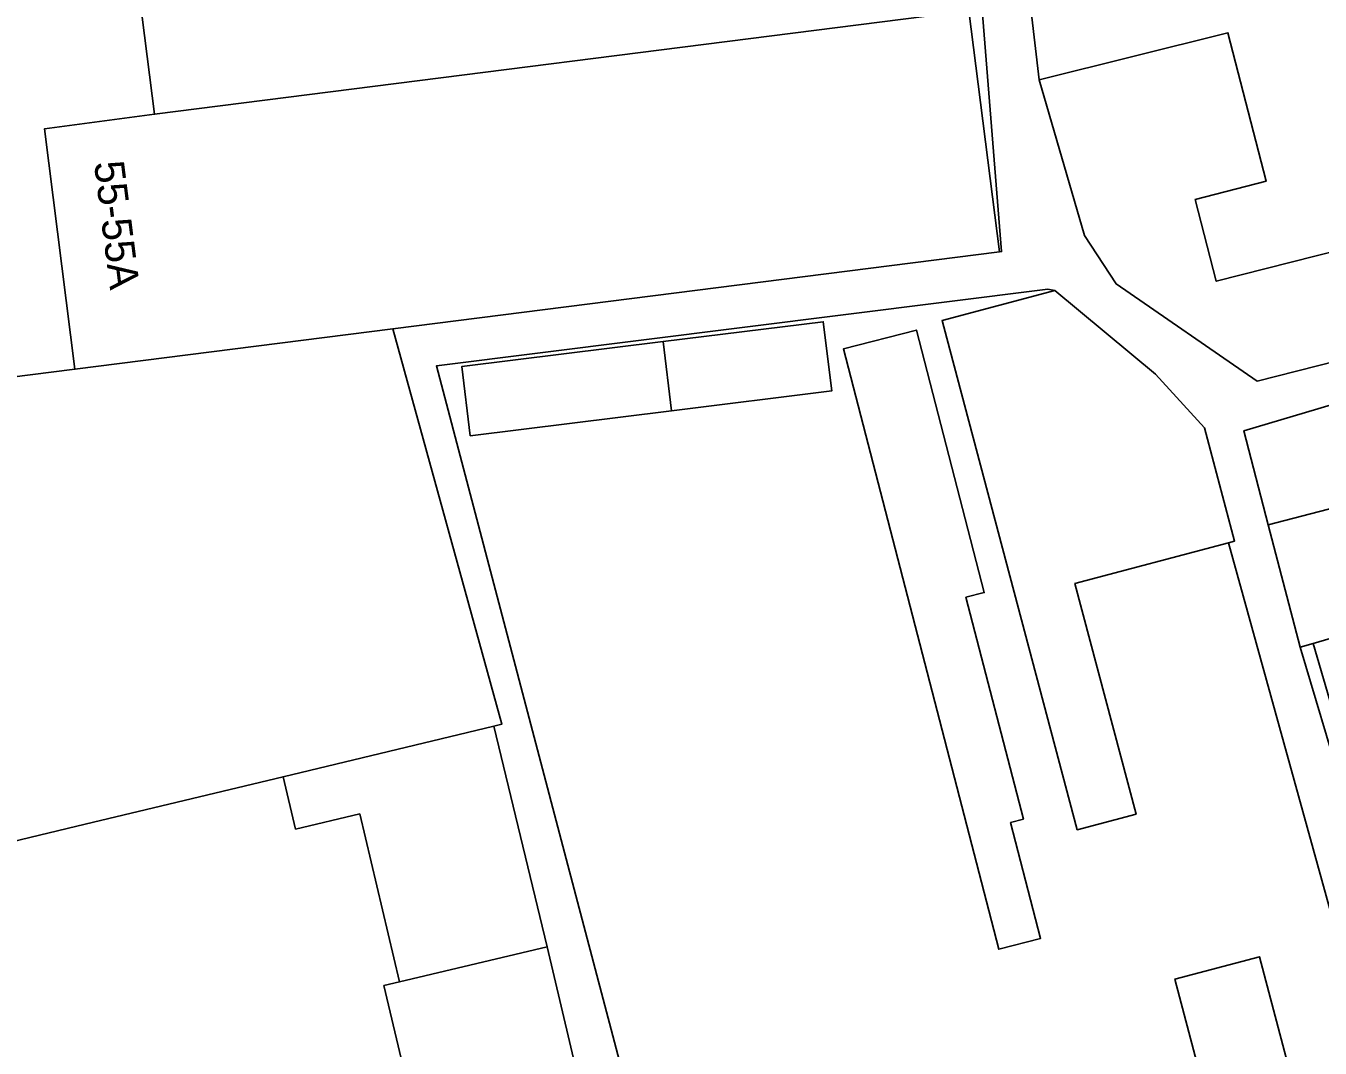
# Model space of a CAD drawing. Extents: x 159262 to 160143, y 383399 to 384319.
# Drawn here: x 159732.84 to 159776.11, y 383835.3 to 383869.47 of the extents above; entities that cross this region are included whole.
import ezdxf

# ---------------------------------------------------------------- set-up
doc = ezdxf.new("R2010")
doc.units = 0
for name, color, linetype in [('IMGEO_Erf', 7, 'Continuous'), ('IMGEO_Pand', 7, 'Continuous'), ('IMGEO_Pand_nummerreeks', 7, 'Continuous'), ('IMGEO_Voetpad_open', 7, 'Continuous')]:
    doc.layers.add(name, color=color, linetype=linetype)

msp = doc.modelspace()

# ---------------------------------------------------------------- linework, layer by layer
at = {"layer": 'IMGEO_Erf'}
for points in [[(159793.775, 383887.604), (159772.878, 383881.969), (159765.598, 383880.005), (159765.664, 383879.758), (159767.81, 383880.351), (159769.144, 383875.373), (159766.998, 383874.78), (159767.047, 383874.596), (159769.706, 383875.08), (159770.298, 383871.831), (159767.071, 383871.242), (159766.479, 383874.492), (159765.932, 383874.341), (159766.711, 383867.668), (159773.026, 383869.247), (159774.305, 383864.282), (159771.931, 383863.67), (159772.634, 383860.939), (159780.947, 383863.051)], [(159764.364, 383869.975), (159765.386, 383861.918), (159765.459, 383861.928), (159764.1, 383878.938)], [(159732.451, 383869.972), (159725.366, 383868.142), (159726.937, 383862.447), (159722.699, 383861.277), (159722.791, 383860.941), (159721.394, 383860.556), (159721.292, 383860.922), (159717.178, 383859.787), (159718.089, 383855.916), (159723.05, 383856.546), (159734.479, 383857.996), (159733.459, 383866.03), (159737.14, 383866.52), (159736.148, 383874.337)], [(159780.061, 383826.825), (159773.045, 383852.196), (159767.91, 383850.833), (159769.956, 383843.125), (159767.985, 383842.602), (159763.624, 383859.035), (159763.467, 383859.625), (159767.243, 383860.627), (159767.004, 383860.67), (159746.562, 383858.112), (159750.904, 383841.626), (159754.397, 383828.364)], [(159784.089, 383859.072), (159773.554, 383855.94), (159774.374, 383852.793), (159776.644, 383853.384)], [(159776.832, 383845.553), (159775.873, 383848.832), (159775.439, 383848.705), (159776.858, 383843.958)], [(159772.809, 383831.702), (159771.253, 383837.61), (159774.075, 383838.359), (159775.641, 383832.453)]]:
    msp.add_lwpolyline(points, dxfattribs=at)
for points in [[(159747.696, 383855.773), (159747.409, 383858.087), (159754.141, 383858.922), (159759.494, 383859.587), (159759.781, 383857.273), (159754.428, 383856.609)], [(159765.365, 383838.607), (159760.169, 383858.676), (159762.609, 383859.308), (159764.88, 383850.534), (159764.265, 383850.374), (159766.187, 383842.952), (159765.757, 383842.841), (159766.76, 383838.969)], [(159744.807, 383837.396), (159745.327, 383837.519), (159743.998, 383843.131), (159741.854, 383842.624), (159741.439, 383844.377), (159734.82, 383842.786), (159730.508, 383841.75), (159730.553, 383841.586), (159731.396, 383838.535), (159732.499, 383834.542), (159734.47, 383827.405), (159731.396, 383826.556), (159726.576, 383825.224), (159726.867, 383824.191), (159731.687, 383825.522), (159736.244, 383826.781), (159737.08, 383823.754), (159742.275, 383825.189), (159747.666, 383826.678), (159746.771, 383829.916), (159751.997, 383831.361), (159751.996, 383831.365), (159746.541, 383830.073)]]:
    msp.add_lwpolyline(points, close=True, dxfattribs=at)
at = {"layer": 'IMGEO_Pand'}
for points in [[(159763.372, 383877.791), (159736.148, 383874.337), (159737.14, 383866.52), (159764.364, 383869.975)], [(159764.364, 383869.975), (159737.14, 383866.52), (159733.459, 383866.03), (159734.479, 383857.996), (159745.107, 383859.345), (159765.386, 383861.918)], [(159773.026, 383869.247), (159766.711, 383867.668), (159768.227, 383862.468), (159769.29, 383860.847), (159774.002, 383857.6), (159782.025, 383859.638), (159781.807, 383860.328), (159781.261, 383862.057), (159780.947, 383863.051), (159772.634, 383860.939), (159771.931, 383863.67), (159774.305, 383864.282)], [(159773.045, 383852.196), (159773.245, 383852.249), (159772.24, 383856.037), (159770.608, 383857.83), (159767.243, 383860.627), (159763.467, 383859.625), (159763.624, 383859.035), (159767.985, 383842.602), (159769.956, 383843.125), (159767.91, 383850.833)], [(159754.141, 383858.922), (159754.428, 383856.609), (159759.781, 383857.273), (159759.494, 383859.587)], [(159745.107, 383859.345), (159734.479, 383857.996), (159723.05, 383856.546), (159718.089, 383855.916), (159718.524, 383854.342), (159720.384, 383854.855), (159721.039, 383852.483), (159719.214, 383851.98), (159719.446, 383851.131), (159720.089, 383848.771), (159720.571, 383847.005), (159721.214, 383844.648), (159721.703, 383842.87), (159722.354, 383840.513), (159722.636, 383839.492), (159730.553, 383841.586), (159730.508, 383841.75), (159734.82, 383842.786), (159741.439, 383844.377), (159748.488, 383846.071), (159748.754, 383846.135)], [(159760.169, 383858.676), (159765.365, 383838.607), (159766.76, 383838.969), (159765.757, 383842.841), (159766.187, 383842.952), (159764.265, 383850.374), (159764.88, 383850.534), (159762.609, 383859.308)], [(159754.141, 383858.922), (159747.409, 383858.087), (159747.696, 383855.773), (159754.428, 383856.609)], [(159776.644, 383853.384), (159774.374, 383852.793), (159775.439, 383848.705), (159775.873, 383848.832), (159777.691, 383849.363)], [(159777.886, 383849.42), (159777.691, 383849.363), (159775.873, 383848.832), (159776.832, 383845.553), (159778.844, 383846.141)], [(159748.488, 383846.071), (159741.439, 383844.377), (159741.854, 383842.624), (159743.998, 383843.131), (159745.327, 383837.519), (159750.262, 383838.688)], [(159750.262, 383838.688), (159745.327, 383837.519), (159744.807, 383837.396), (159746.541, 383830.073), (159751.996, 383831.365)], [(159772.809, 383831.702), (159775.641, 383832.453), (159774.075, 383838.359), (159771.253, 383837.61)]]:
    msp.add_lwpolyline(points, close=True, dxfattribs=at)
at = {"layer": 'IMGEO_Voetpad_open'}
for points in [[(159782.025, 383859.638), (159774.002, 383857.6), (159769.29, 383860.847), (159768.227, 383862.468), (159766.711, 383867.668), (159765.932, 383874.341), (159766.479, 383874.492), (159767.047, 383874.596), (159766.998, 383874.78), (159766.112, 383878.086), (159765.664, 383879.758), (159765.598, 383880.005), (159772.878, 383881.969), (159793.775, 383887.604)], [(159764.1, 383878.938), (159765.459, 383861.928), (159765.386, 383861.918), (159745.107, 383859.345), (159748.754, 383846.135), (159748.488, 383846.071), (159750.262, 383838.688), (159751.996, 383831.365)], [(159754.397, 383828.364), (159750.904, 383841.626), (159746.562, 383858.112), (159767.004, 383860.67), (159767.243, 383860.627), (159770.608, 383857.83), (159772.24, 383856.037), (159773.245, 383852.249), (159773.045, 383852.196), (159780.061, 383826.825)], [(159776.858, 383843.958), (159775.439, 383848.705), (159774.374, 383852.793), (159773.554, 383855.94), (159784.089, 383859.072)]]:
    msp.add_lwpolyline(points, dxfattribs=at)

# ---------------------------------------------------------------- texts
at = {"layer": 'IMGEO_Pand_nummerreeks'}
msp.add_text('55-55A', height=1, rotation=277.2362, dxfattribs=at).set_placement((159735.114, 383864.902))

doc.saveas('drawing.dxf')
